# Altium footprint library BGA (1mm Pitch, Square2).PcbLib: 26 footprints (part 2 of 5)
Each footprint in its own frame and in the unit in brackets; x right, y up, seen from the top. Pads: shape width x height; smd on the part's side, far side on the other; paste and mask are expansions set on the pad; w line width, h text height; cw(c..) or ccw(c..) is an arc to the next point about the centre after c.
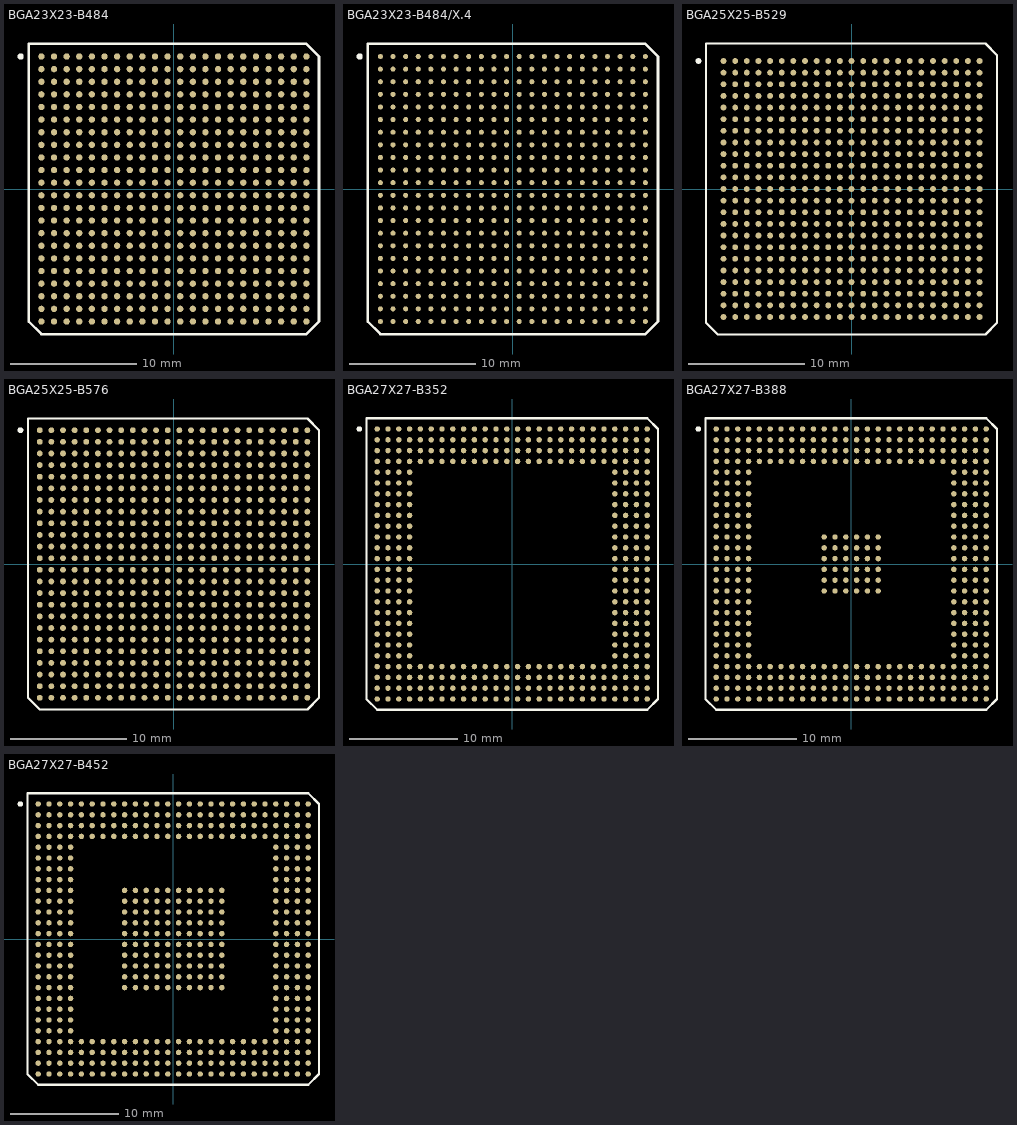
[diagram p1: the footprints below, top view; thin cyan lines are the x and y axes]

## BGA23X23-B484 [mm]
pads (484):
  round 0.5 smd: A1(-10.5,10.5) A2(-9.5,10.5) A3(-8.5,10.5) A4(-7.5,10.5) A5(-6.5,10.5) A6(-5.5,10.5) A7(-4.5,10.5) A8(-3.5,10.5) A9(-2.5,10.5) A10(-1.5,10.5) A11(-0.5,10.5) A12(0.5,10.5) A13(1.5,10.5) A14(2.5,10.5) A15(3.5,10.5) A16(4.5,10.5) A17(5.5,10.5) A18(6.5,10.5) A19(7.5,10.5) A20(8.5,10.5) A21(9.5,10.5) A22(10.5,10.5) AA1(-10.5,-9.5) AA2(-9.5,-9.5) AA3(-8.5,-9.5) AA4(-7.5,-9.5) AA5(-6.5,-9.5) AA6(-5.5,-9.5) AA7(-4.5,-9.5) AA8(-3.5,-9.5) AA9(-2.5,-9.5) AA10(-1.5,-9.5) AA11(-0.5,-9.5) AA12(0.5,-9.5) AA13(1.5,-9.5) AA14(2.5,-9.5) AA15(3.5,-9.5) AA16(4.5,-9.5) AA17(5.5,-9.5) AA18(6.5,-9.5) AA19(7.5,-9.5) AA20(8.5,-9.5) AA21(9.5,-9.5) AA22(10.5,-9.5) AB1(-10.5,-10.5) AB2(-9.5,-10.5) AB3(-8.5,-10.5) AB4(-7.5,-10.5) AB5(-6.5,-10.5) AB6(-5.5,-10.5) AB7(-4.5,-10.5) AB8(-3.5,-10.5) AB9(-2.5,-10.5) AB10(-1.5,-10.5) AB11(-0.5,-10.5) AB12(0.5,-10.5) AB13(1.5,-10.5) AB14(2.5,-10.5) AB15(3.5,-10.5) AB16(4.5,-10.5) AB17(5.5,-10.5) AB18(6.5,-10.5) AB19(7.5,-10.5) AB20(8.5,-10.5) AB21(9.5,-10.5) AB22(10.5,-10.5) B1(-10.5,9.5) B2(-9.5,9.5) B3(-8.5,9.5) B4(-7.5,9.5) B5(-6.5,9.5) B6(-5.5,9.5) B7(-4.5,9.5) B8(-3.5,9.5) B9(-2.5,9.5) B10(-1.5,9.5) B11(-0.5,9.5) B12(0.5,9.5) B13(1.5,9.5) B14(2.5,9.5) B15(3.5,9.5) B16(4.5,9.5) B17(5.5,9.5) B18(6.5,9.5) B19(7.5,9.5) B20(8.5,9.5) B21(9.5,9.5) B22(10.5,9.5) C1(-10.5,8.5) C2(-9.5,8.5) C3(-8.5,8.5) C4(-7.5,8.5) C5(-6.5,8.5) C6(-5.5,8.5) C7(-4.5,8.5) C8(-3.5,8.5) C9(-2.5,8.5) C10(-1.5,8.5) C11(-0.5,8.5) C12(0.5,8.5) C13(1.5,8.5) C14(2.5,8.5) C15(3.5,8.5) C16(4.5,8.5) C17(5.5,8.5) C18(6.5,8.5) C19(7.5,8.5) C20(8.5,8.5) C21(9.5,8.5) C22(10.5,8.5) D1(-10.5,7.5) D2(-9.5,7.5) D3(-8.5,7.5) D4(-7.5,7.5) D5(-6.5,7.5) D6(-5.5,7.5) D7(-4.5,7.5) D8(-3.5,7.5) D9(-2.5,7.5) D10(-1.5,7.5) D11(-0.5,7.5) D12(0.5,7.5) D13(1.5,7.5) D14(2.5,7.5) D15(3.5,7.5) D16(4.5,7.5) D17(5.5,7.5) D18(6.5,7.5) D19(7.5,7.5) D20(8.5,7.5) D21(9.5,7.5) D22(10.5,7.5) E1(-10.5,6.5) E2(-9.5,6.5) E3(-8.5,6.5) E4(-7.5,6.5) E5(-6.5,6.5) E6(-5.5,6.5) E7(-4.5,6.5) E8(-3.5,6.5) E9(-2.5,6.5) E10(-1.5,6.5) E11(-0.5,6.5) E12(0.5,6.5) E13(1.5,6.5) E14(2.5,6.5) E15(3.5,6.5) E16(4.5,6.5) E17(5.5,6.5) E18(6.5,6.5) E19(7.5,6.5) E20(8.5,6.5) E21(9.5,6.5) E22(10.5,6.5) F1(-10.5,5.5) F2(-9.5,5.5) F3(-8.5,5.5) F4(-7.5,5.5) F5(-6.5,5.5) F6(-5.5,5.5) F7(-4.5,5.5) F8(-3.5,5.5) F9(-2.5,5.5) F10(-1.5,5.5) F11(-0.5,5.5) F12(0.5,5.5) F13(1.5,5.5) F14(2.5,5.5) F15(3.5,5.5) F16(4.5,5.5) F17(5.5,5.5) F18(6.5,5.5) F19(7.5,5.5) F20(8.5,5.5) F21(9.5,5.5) F22(10.5,5.5) G1(-10.5,4.5) G2(-9.5,4.5) G3(-8.5,4.5) G4(-7.5,4.5) G5(-6.5,4.5) G6(-5.5,4.5) G7(-4.5,4.5) G8(-3.5,4.5) G9(-2.5,4.5) G10(-1.5,4.5) G11(-0.5,4.5) G12(0.5,4.5) G13(1.5,4.5) G14(2.5,4.5) G15(3.5,4.5) G16(4.5,4.5) G17(5.5,4.5) G18(6.5,4.5) G19(7.5,4.5) G20(8.5,4.5) G21(9.5,4.5) G22(10.5,4.5) H1(-10.5,3.5) H2(-9.5,3.5) H3(-8.5,3.5) H4(-7.5,3.5) H5(-6.5,3.5) H6(-5.5,3.5) H7(-4.5,3.5) H8(-3.5,3.5) H9(-2.5,3.5) H10(-1.5,3.5) H11(-0.5,3.5) H12(0.5,3.5) H13(1.5,3.5) H14(2.5,3.5) H15(3.5,3.5) H16(4.5,3.5) H17(5.5,3.5) H18(6.5,3.5) H19(7.5,3.5) H20(8.5,3.5) H21(9.5,3.5) H22(10.5,3.5) J1(-10.5,2.5) J2(-9.5,2.5) J3(-8.5,2.5) J4(-7.5,2.5) J5(-6.5,2.5) J6(-5.5,2.5) J7(-4.5,2.5) J8(-3.5,2.5) J9(-2.5,2.5) J10(-1.5,2.5) J11(-0.5,2.5) J12(0.5,2.5) J13(1.5,2.5) J14(2.5,2.5) J15(3.5,2.5) J16(4.5,2.5) J17(5.5,2.5) J18(6.5,2.5) J19(7.5,2.5) J20(8.5,2.5) J21(9.5,2.5) J22(10.5,2.5) K1(-10.5,1.5) K2(-9.5,1.5) K3(-8.5,1.5) K4(-7.5,1.5) K5(-6.5,1.5) K6(-5.5,1.5) K7(-4.5,1.5) K8(-3.5,1.5) K9(-2.5,1.5) K10(-1.5,1.5) K11(-0.5,1.5) K12(0.5,1.5) K13(1.5,1.5) K14(2.5,1.5) K15(3.5,1.5) K16(4.5,1.5) K17(5.5,1.5) K18(6.5,1.5) K19(7.5,1.5) K20(8.5,1.5) K21(9.5,1.5) K22(10.5,1.5) L1(-10.5,0.5) L2(-9.5,0.5) L3(-8.5,0.5) L4(-7.5,0.5) L5(-6.5,0.5) L6(-5.5,0.5) L7(-4.5,0.5) L8(-3.5,0.5) L9(-2.5,0.5) L10(-1.5,0.5) L11(-0.5,0.5) L12(0.5,0.5) L13(1.5,0.5) L14(2.5,0.5) L15(3.5,0.5) L16(4.5,0.5) L17(5.5,0.5) L18(6.5,0.5) L19(7.5,0.5) L20(8.5,0.5) L21(9.5,0.5) L22(10.5,0.5) M1(-10.5,-0.5) M2(-9.5,-0.5) M3(-8.5,-0.5) M4(-7.5,-0.5) M5(-6.5,-0.5) M6(-5.5,-0.5) M7(-4.5,-0.5) M8(-3.5,-0.5) M9(-2.5,-0.5) M10(-1.5,-0.5) M11(-0.5,-0.5) M12(0.5,-0.5) M13(1.5,-0.5) M14(2.5,-0.5) M15(3.5,-0.5) M16(4.5,-0.5) M17(5.5,-0.5) M18(6.5,-0.5) M19(7.5,-0.5) M20(8.5,-0.5) M21(9.5,-0.5) M22(10.5,-0.5) N1(-10.5,-1.5) N2(-9.5,-1.5) N3(-8.5,-1.5) N4(-7.5,-1.5) N5(-6.5,-1.5) N6(-5.5,-1.5) N7(-4.5,-1.5) N8(-3.5,-1.5) N9(-2.5,-1.5) N10(-1.5,-1.5) N11(-0.5,-1.5) N12(0.5,-1.5) N13(1.5,-1.5) N14(2.5,-1.5) N15(3.5,-1.5) N16(4.5,-1.5) N17(5.5,-1.5) N18(6.5,-1.5) N19(7.5,-1.5) N20(8.5,-1.5) N21(9.5,-1.5) N22(10.5,-1.5) P1(-10.5,-2.5) P2(-9.5,-2.5) P3(-8.5,-2.5) P4(-7.5,-2.5) P5(-6.5,-2.5) P6(-5.5,-2.5) P7(-4.5,-2.5) P8(-3.5,-2.5) P9(-2.5,-2.5) P10(-1.5,-2.5) P11(-0.5,-2.5) P12(0.5,-2.5) P13(1.5,-2.5) P14(2.5,-2.5) P15(3.5,-2.5) P16(4.5,-2.5) P17(5.5,-2.5) P18(6.5,-2.5) P19(7.5,-2.5) P20(8.5,-2.5) P21(9.5,-2.5) P22(10.5,-2.5) R1(-10.5,-3.5) R2(-9.5,-3.5) R3(-8.5,-3.5) R4(-7.5,-3.5) R5(-6.5,-3.5) R6(-5.5,-3.5) R7(-4.5,-3.5) R8(-3.5,-3.5) R9(-2.5,-3.5) R10(-1.5,-3.5) R11(-0.5,-3.5) R12(0.5,-3.5) R13(1.5,-3.5) R14(2.5,-3.5) R15(3.5,-3.5) R16(4.5,-3.5) R17(5.5,-3.5) R18(6.5,-3.5) R19(7.5,-3.5) R20(8.5,-3.5) R21(9.5,-3.5) R22(10.5,-3.5) T1(-10.5,-4.5) T2(-9.5,-4.5) T3(-8.5,-4.5) T4(-7.5,-4.5) T5(-6.5,-4.5) T6(-5.5,-4.5) T7(-4.5,-4.5) T8(-3.5,-4.5) T9(-2.5,-4.5) T10(-1.5,-4.5) T11(-0.5,-4.5) T12(0.5,-4.5) T13(1.5,-4.5) T14(2.5,-4.5) T15(3.5,-4.5) T16(4.5,-4.5) T17(5.5,-4.5) T18(6.5,-4.5) T19(7.5,-4.5) T20(8.5,-4.5) T21(9.5,-4.5) T22(10.5,-4.5) U1(-10.5,-5.5) U2(-9.5,-5.5) U3(-8.5,-5.5) U4(-7.5,-5.5) U5(-6.5,-5.5) U6(-5.5,-5.5) U7(-4.5,-5.5) U8(-3.5,-5.5) U9(-2.5,-5.5) U10(-1.5,-5.5) U11(-0.5,-5.5) U12(0.5,-5.5) U13(1.5,-5.5) U14(2.5,-5.5) U15(3.5,-5.5) U16(4.5,-5.5) U17(5.5,-5.5) U18(6.5,-5.5) U19(7.5,-5.5) U20(8.5,-5.5) U21(9.5,-5.5) U22(10.5,-5.5) V1(-10.5,-6.5) V2(-9.5,-6.5) V3(-8.5,-6.5) V4(-7.5,-6.5) V5(-6.5,-6.5) V6(-5.5,-6.5) V7(-4.5,-6.5) V8(-3.5,-6.5) V9(-2.5,-6.5) V10(-1.5,-6.5) V11(-0.5,-6.5) V12(0.5,-6.5) V13(1.5,-6.5) V14(2.5,-6.5) V15(3.5,-6.5) V16(4.5,-6.5) V17(5.5,-6.5) V18(6.5,-6.5) V19(7.5,-6.5) V20(8.5,-6.5) V21(9.5,-6.5) V22(10.5,-6.5) W1(-10.5,-7.5) W2(-9.5,-7.5) W3(-8.5,-7.5) W4(-7.5,-7.5) W5(-6.5,-7.5) W6(-5.5,-7.5) W7(-4.5,-7.5) W8(-3.5,-7.5) W9(-2.5,-7.5) W10(-1.5,-7.5) W11(-0.5,-7.5) W12(0.5,-7.5) W13(1.5,-7.5) W14(2.5,-7.5) W15(3.5,-7.5) W16(4.5,-7.5) W17(5.5,-7.5) W18(6.5,-7.5) W19(7.5,-7.5) W20(8.5,-7.5) W21(9.5,-7.5) W22(10.5,-7.5) Y1(-10.5,-8.5) Y2(-9.5,-8.5) Y3(-8.5,-8.5) Y4(-7.5,-8.5) Y5(-6.5,-8.5) Y6(-5.5,-8.5) Y7(-4.5,-8.5) Y8(-3.5,-8.5) Y9(-2.5,-8.5) Y10(-1.5,-8.5) Y11(-0.5,-8.5) Y12(0.5,-8.5) Y13(1.5,-8.5) Y14(2.5,-8.5) Y15(3.5,-8.5) Y16(4.5,-8.5) Y17(5.5,-8.5) Y18(6.5,-8.5) Y19(7.5,-8.5) Y20(8.5,-8.5) Y21(9.5,-8.5) Y22(10.5,-8.5)
Top Overlay:
  circle w0.25: c-12.15,10.5 r0.125
  lines w0.2: 10.5,-11.5 11.5,-10.5 11.5,10.5 ; 10.5,-11.5 10.5,-11.5 ; 10.5,-11.5 -10.5,-11.5 -11.5,-10.5 -11.5,11.5 10.5,11.5 11.5,10.5 ; 11.5,10.5 11.5,10.5

## BGA23X23-B484/X.4 [mm]
pads (484):
  round 0.4 smd: A1(-10.5,10.5) A2(-9.5,10.5) A3(-8.5,10.5) A4(-7.5,10.5) A5(-6.5,10.5) A6(-5.5,10.5) A7(-4.5,10.5) A8(-3.5,10.5) A9(-2.5,10.5) A10(-1.5,10.5) A11(-0.5,10.5) A12(0.5,10.5) A13(1.5,10.5) A14(2.5,10.5) A15(3.5,10.5) A16(4.5,10.5) A17(5.5,10.5) A18(6.5,10.5) A19(7.5,10.5) A20(8.5,10.5) A21(9.5,10.5) A22(10.5,10.5) AA1(-10.5,-9.5) AA2(-9.5,-9.5) AA3(-8.5,-9.5) AA4(-7.5,-9.5) AA5(-6.5,-9.5) AA6(-5.5,-9.5) AA7(-4.5,-9.5) AA8(-3.5,-9.5) AA9(-2.5,-9.5) AA10(-1.5,-9.5) AA11(-0.5,-9.5) AA12(0.5,-9.5) AA13(1.5,-9.5) AA14(2.5,-9.5) AA15(3.5,-9.5) AA16(4.5,-9.5) AA17(5.5,-9.5) AA18(6.5,-9.5) AA19(7.5,-9.5) AA20(8.5,-9.5) AA21(9.5,-9.5) AA22(10.5,-9.5) AB1(-10.5,-10.5) AB2(-9.5,-10.5) AB3(-8.5,-10.5) AB4(-7.5,-10.5) AB5(-6.5,-10.5) AB6(-5.5,-10.5) AB7(-4.5,-10.5) AB8(-3.5,-10.5) AB9(-2.5,-10.5) AB10(-1.5,-10.5) AB11(-0.5,-10.5) AB12(0.5,-10.5) AB13(1.5,-10.5) AB14(2.5,-10.5) AB15(3.5,-10.5) AB16(4.5,-10.5) AB17(5.5,-10.5) AB18(6.5,-10.5) AB19(7.5,-10.5) AB20(8.5,-10.5) AB21(9.5,-10.5) AB22(10.5,-10.5) B1(-10.5,9.5) B2(-9.5,9.5) B3(-8.5,9.5) B4(-7.5,9.5) B5(-6.5,9.5) B6(-5.5,9.5) B7(-4.5,9.5) B8(-3.5,9.5) B9(-2.5,9.5) B10(-1.5,9.5) B11(-0.5,9.5) B12(0.5,9.5) B13(1.5,9.5) B14(2.5,9.5) B15(3.5,9.5) B16(4.5,9.5) B17(5.5,9.5) B18(6.5,9.5) B19(7.5,9.5) B20(8.5,9.5) B21(9.5,9.5) B22(10.5,9.5) C1(-10.5,8.5) C2(-9.5,8.5) C3(-8.5,8.5) C4(-7.5,8.5) C5(-6.5,8.5) C6(-5.5,8.5) C7(-4.5,8.5) C8(-3.5,8.5) C9(-2.5,8.5) C10(-1.5,8.5) C11(-0.5,8.5) C12(0.5,8.5) C13(1.5,8.5) C14(2.5,8.5) C15(3.5,8.5) C16(4.5,8.5) C17(5.5,8.5) C18(6.5,8.5) C19(7.5,8.5) C20(8.5,8.5) C21(9.5,8.5) C22(10.5,8.5) D1(-10.5,7.5) D2(-9.5,7.5) D3(-8.5,7.5) D4(-7.5,7.5) D5(-6.5,7.5) D6(-5.5,7.5) D7(-4.5,7.5) D8(-3.5,7.5) D9(-2.5,7.5) D10(-1.5,7.5) D11(-0.5,7.5) D12(0.5,7.5) D13(1.5,7.5) D14(2.5,7.5) D15(3.5,7.5) D16(4.5,7.5) D17(5.5,7.5) D18(6.5,7.5) D19(7.5,7.5) D20(8.5,7.5) D21(9.5,7.5) D22(10.5,7.5) E1(-10.5,6.5) E2(-9.5,6.5) E3(-8.5,6.5) E4(-7.5,6.5) E5(-6.5,6.5) E6(-5.5,6.5) E7(-4.5,6.5) E8(-3.5,6.5) E9(-2.5,6.5) E10(-1.5,6.5) E11(-0.5,6.5) E12(0.5,6.5) E13(1.5,6.5) E14(2.5,6.5) E15(3.5,6.5) E16(4.5,6.5) E17(5.5,6.5) E18(6.5,6.5) E19(7.5,6.5) E20(8.5,6.5) E21(9.5,6.5) E22(10.5,6.5) F1(-10.5,5.5) F2(-9.5,5.5) F3(-8.5,5.5) F4(-7.5,5.5) F5(-6.5,5.5) F6(-5.5,5.5) F7(-4.5,5.5) F8(-3.5,5.5) F9(-2.5,5.5) F10(-1.5,5.5) F11(-0.5,5.5) F12(0.5,5.5) F13(1.5,5.5) F14(2.5,5.5) F15(3.5,5.5) F16(4.5,5.5) F17(5.5,5.5) F18(6.5,5.5) F19(7.5,5.5) F20(8.5,5.5) F21(9.5,5.5) F22(10.5,5.5) G1(-10.5,4.5) G2(-9.5,4.5) G3(-8.5,4.5) G4(-7.5,4.5) G5(-6.5,4.5) G6(-5.5,4.5) G7(-4.5,4.5) G8(-3.5,4.5) G9(-2.5,4.5) G10(-1.5,4.5) G11(-0.5,4.5) G12(0.5,4.5) G13(1.5,4.5) G14(2.5,4.5) G15(3.5,4.5) G16(4.5,4.5) G17(5.5,4.5) G18(6.5,4.5) G19(7.5,4.5) G20(8.5,4.5) G21(9.5,4.5) G22(10.5,4.5) H1(-10.5,3.5) H2(-9.5,3.5) H3(-8.5,3.5) H4(-7.5,3.5) H5(-6.5,3.5) H6(-5.5,3.5) H7(-4.5,3.5) H8(-3.5,3.5) H9(-2.5,3.5) H10(-1.5,3.5) H11(-0.5,3.5) H12(0.5,3.5) H13(1.5,3.5) H14(2.5,3.5) H15(3.5,3.5) H16(4.5,3.5) H17(5.5,3.5) H18(6.5,3.5) H19(7.5,3.5) H20(8.5,3.5) H21(9.5,3.5) H22(10.5,3.5) J1(-10.5,2.5) J2(-9.5,2.5) J3(-8.5,2.5) J4(-7.5,2.5) J5(-6.5,2.5) J6(-5.5,2.5) J7(-4.5,2.5) J8(-3.5,2.5) J9(-2.5,2.5) J10(-1.5,2.5) J11(-0.5,2.5) J12(0.5,2.5) J13(1.5,2.5) J14(2.5,2.5) J15(3.5,2.5) J16(4.5,2.5) J17(5.5,2.5) J18(6.5,2.5) J19(7.5,2.5) J20(8.5,2.5) J21(9.5,2.5) J22(10.5,2.5) K1(-10.5,1.5) K2(-9.5,1.5) K3(-8.5,1.5) K4(-7.5,1.5) K5(-6.5,1.5) K6(-5.5,1.5) K7(-4.5,1.5) K8(-3.5,1.5) K9(-2.5,1.5) K10(-1.5,1.5) K11(-0.5,1.5) K12(0.5,1.5) K13(1.5,1.5) K14(2.5,1.5) K15(3.5,1.5) K16(4.5,1.5) K17(5.5,1.5) K18(6.5,1.5) K19(7.5,1.5) K20(8.5,1.5) K21(9.5,1.5) K22(10.5,1.5) L1(-10.5,0.5) L2(-9.5,0.5) L3(-8.5,0.5) L4(-7.5,0.5) L5(-6.5,0.5) L6(-5.5,0.5) L7(-4.5,0.5) L8(-3.5,0.5) L9(-2.5,0.5) L10(-1.5,0.5) L11(-0.5,0.5) L12(0.5,0.5) L13(1.5,0.5) L14(2.5,0.5) L15(3.5,0.5) L16(4.5,0.5) L17(5.5,0.5) L18(6.5,0.5) L19(7.5,0.5) L20(8.5,0.5) L21(9.5,0.5) L22(10.5,0.5) M1(-10.5,-0.5) M2(-9.5,-0.5) M3(-8.5,-0.5) M4(-7.5,-0.5) M5(-6.5,-0.5) M6(-5.5,-0.5) M7(-4.5,-0.5) M8(-3.5,-0.5) M9(-2.5,-0.5) M10(-1.5,-0.5) M11(-0.5,-0.5) M12(0.5,-0.5) M13(1.5,-0.5) M14(2.5,-0.5) M15(3.5,-0.5) M16(4.5,-0.5) M17(5.5,-0.5) M18(6.5,-0.5) M19(7.5,-0.5) M20(8.5,-0.5) M21(9.5,-0.5) M22(10.5,-0.5) N1(-10.5,-1.5) N2(-9.5,-1.5) N3(-8.5,-1.5) N4(-7.5,-1.5) N5(-6.5,-1.5) N6(-5.5,-1.5) N7(-4.5,-1.5) N8(-3.5,-1.5) N9(-2.5,-1.5) N10(-1.5,-1.5) N11(-0.5,-1.5) N12(0.5,-1.5) N13(1.5,-1.5) N14(2.5,-1.5) N15(3.5,-1.5) N16(4.5,-1.5) N17(5.5,-1.5) N18(6.5,-1.5) N19(7.5,-1.5) N20(8.5,-1.5) N21(9.5,-1.5) N22(10.5,-1.5) P1(-10.5,-2.5) P2(-9.5,-2.5) P3(-8.5,-2.5) P4(-7.5,-2.5) P5(-6.5,-2.5) P6(-5.5,-2.5) P7(-4.5,-2.5) P8(-3.5,-2.5) P9(-2.5,-2.5) P10(-1.5,-2.5) P11(-0.5,-2.5) P12(0.5,-2.5) P13(1.5,-2.5) P14(2.5,-2.5) P15(3.5,-2.5) P16(4.5,-2.5) P17(5.5,-2.5) P18(6.5,-2.5) P19(7.5,-2.5) P20(8.5,-2.5) P21(9.5,-2.5) P22(10.5,-2.5) R1(-10.5,-3.5) R2(-9.5,-3.5) R3(-8.5,-3.5) R4(-7.5,-3.5) R5(-6.5,-3.5) R6(-5.5,-3.5) R7(-4.5,-3.5) R8(-3.5,-3.5) R9(-2.5,-3.5) R10(-1.5,-3.5) R11(-0.5,-3.5) R12(0.5,-3.5) R13(1.5,-3.5) R14(2.5,-3.5) R15(3.5,-3.5) R16(4.5,-3.5) R17(5.5,-3.5) R18(6.5,-3.5) R19(7.5,-3.5) R20(8.5,-3.5) R21(9.5,-3.5) R22(10.5,-3.5) T1(-10.5,-4.5) T2(-9.5,-4.5) T3(-8.5,-4.5) T4(-7.5,-4.5) T5(-6.5,-4.5) T6(-5.5,-4.5) T7(-4.5,-4.5) T8(-3.5,-4.5) T9(-2.5,-4.5) T10(-1.5,-4.5) T11(-0.5,-4.5) T12(0.5,-4.5) T13(1.5,-4.5) T14(2.5,-4.5) T15(3.5,-4.5) T16(4.5,-4.5) T17(5.5,-4.5) T18(6.5,-4.5) T19(7.5,-4.5) T20(8.5,-4.5) T21(9.5,-4.5) T22(10.5,-4.5) U1(-10.5,-5.5) U2(-9.5,-5.5) U3(-8.5,-5.5) U4(-7.5,-5.5) U5(-6.5,-5.5) U6(-5.5,-5.5) U7(-4.5,-5.5) U8(-3.5,-5.5) U9(-2.5,-5.5) U10(-1.5,-5.5) U11(-0.5,-5.5) U12(0.5,-5.5) U13(1.5,-5.5) U14(2.5,-5.5) U15(3.5,-5.5) U16(4.5,-5.5) U17(5.5,-5.5) U18(6.5,-5.5) U19(7.5,-5.5) U20(8.5,-5.5) U21(9.5,-5.5) U22(10.5,-5.5) V1(-10.5,-6.5) V2(-9.5,-6.5) V3(-8.5,-6.5) V4(-7.5,-6.5) V5(-6.5,-6.5) V6(-5.5,-6.5) V7(-4.5,-6.5) V8(-3.5,-6.5) V9(-2.5,-6.5) V10(-1.5,-6.5) V11(-0.5,-6.5) V12(0.5,-6.5) V13(1.5,-6.5) V14(2.5,-6.5) V15(3.5,-6.5) V16(4.5,-6.5) V17(5.5,-6.5) V18(6.5,-6.5) V19(7.5,-6.5) V20(8.5,-6.5) V21(9.5,-6.5) V22(10.5,-6.5) W1(-10.5,-7.5) W2(-9.5,-7.5) W3(-8.5,-7.5) W4(-7.5,-7.5) W5(-6.5,-7.5) W6(-5.5,-7.5) W7(-4.5,-7.5) W8(-3.5,-7.5) W9(-2.5,-7.5) W10(-1.5,-7.5) W11(-0.5,-7.5) W12(0.5,-7.5) W13(1.5,-7.5) W14(2.5,-7.5) W15(3.5,-7.5) W16(4.5,-7.5) W17(5.5,-7.5) W18(6.5,-7.5) W19(7.5,-7.5) W20(8.5,-7.5) W21(9.5,-7.5) W22(10.5,-7.5) Y1(-10.5,-8.5) Y2(-9.5,-8.5) Y3(-8.5,-8.5) Y4(-7.5,-8.5) Y5(-6.5,-8.5) Y6(-5.5,-8.5) Y7(-4.5,-8.5) Y8(-3.5,-8.5) Y9(-2.5,-8.5) Y10(-1.5,-8.5) Y11(-0.5,-8.5) Y12(0.5,-8.5) Y13(1.5,-8.5) Y14(2.5,-8.5) Y15(3.5,-8.5) Y16(4.5,-8.5) Y17(5.5,-8.5) Y18(6.5,-8.5) Y19(7.5,-8.5) Y20(8.5,-8.5) Y21(9.5,-8.5) Y22(10.5,-8.5)
Top Overlay:
  circle w0.25: c-12.15,10.5 r0.125
  lines w0.2: -11.5,-10.5 -10.5,-11.5 10.5,-11.5 11.5,-10.5 11.5,10.5 10.5,11.5 -11.5,11.5 -11.5,-10.5

## BGA25X25-B529 [mm]
pads (529):
  round 0.5 smd: A1(-11,11) A2(-10,11) A3(-9,11) A4(-8,11) A5(-7,11) A6(-6,11) A7(-5,11) A8(-4,11) A9(-3,11) A10(-2,11) A11(-1,11) A12(0,11) A13(1,11) A14(2,11) A15(3,11) A16(4,11) A17(5,11) A18(6,11) A19(7,11) A20(8,11) A21(9,11) A22(10,11) A23(11,11) AA1(-11,-9) AA2(-10,-9) AA3(-9,-9) AA4(-8,-9) AA5(-7,-9) AA6(-6,-9) AA7(-5,-9) AA8(-4,-9) AA9(-3,-9) AA10(-2,-9) AA11(-1,-9) AA12(0,-9) AA13(1,-9) AA14(2,-9) AA15(3,-9) AA16(4,-9) AA17(5,-9) AA18(6,-9) AA19(7,-9) AA20(8,-9) AA21(9,-9) AA22(10,-9) AA23(11,-9) AB1(-11,-10) AB2(-10,-10) AB3(-9,-10) AB4(-8,-10) AB5(-7,-10) AB6(-6,-10) AB7(-5,-10) AB8(-4,-10) AB9(-3,-10) AB10(-2,-10) AB11(-1,-10) AB12(0,-10) AB13(1,-10) AB14(2,-10) AB15(3,-10) AB16(4,-10) AB17(5,-10) AB18(6,-10) AB19(7,-10) AB20(8,-10) AB21(9,-10) AB22(10,-10) AB23(11,-10) AC1(-11,-11) AC2(-10,-11) AC3(-9,-11) AC4(-8,-11) AC5(-7,-11) AC6(-6,-11) AC7(-5,-11) AC8(-4,-11) AC9(-3,-11) AC10(-2,-11) AC11(-1,-11) AC12(0,-11) AC13(1,-11) AC14(2,-11) AC15(3,-11) AC16(4,-11) AC17(5,-11) AC18(6,-11) AC19(7,-11) AC20(8,-11) AC21(9,-11) AC22(10,-11) AC23(11,-11) B1(-11,10) B2(-10,10) B3(-9,10) B4(-8,10) B5(-7,10) B6(-6,10) B7(-5,10) B8(-4,10) B9(-3,10) B10(-2,10) B11(-1,10) B12(0,10) B13(1,10) B14(2,10) B15(3,10) B16(4,10) B17(5,10) B18(6,10) B19(7,10) B20(8,10) B21(9,10) B22(10,10) B23(11,10) C1(-11,9) C2(-10,9) C3(-9,9) C4(-8,9) C5(-7,9) C6(-6,9) C7(-5,9) C8(-4,9) C9(-3,9) C10(-2,9) C11(-1,9) C12(0,9) C13(1,9) C14(2,9) C15(3,9) C16(4,9) C17(5,9) C18(6,9) C19(7,9) C20(8,9) C21(9,9) C22(10,9) C23(11,9) D1(-11,8) D2(-10,8) D3(-9,8) D4(-8,8) D5(-7,8) D6(-6,8) D7(-5,8) D8(-4,8) D9(-3,8) D10(-2,8) D11(-1,8) D12(0,8) D13(1,8) D14(2,8) D15(3,8) D16(4,8) D17(5,8) D18(6,8) D19(7,8) D20(8,8) D21(9,8) D22(10,8) D23(11,8) E1(-11,7) E2(-10,7) E3(-9,7) E4(-8,7) E5(-7,7) E6(-6,7) E7(-5,7) E8(-4,7) E9(-3,7) E10(-2,7) E11(-1,7) E12(0,7) E13(1,7) E14(2,7) E15(3,7) E16(4,7) E17(5,7) E18(6,7) E19(7,7) E20(8,7) E21(9,7) E22(10,7) E23(11,7) F1(-11,6) F2(-10,6) F3(-9,6) F4(-8,6) F5(-7,6) F6(-6,6) F7(-5,6) F8(-4,6) F9(-3,6) F10(-2,6) F11(-1,6) F12(0,6) F13(1,6) F14(2,6) F15(3,6) F16(4,6) F17(5,6) F18(6,6) F19(7,6) F20(8,6) F21(9,6) F22(10,6) F23(11,6) G1(-11,5) G2(-10,5) G3(-9,5) G4(-8,5) G5(-7,5) G6(-6,5) G7(-5,5) G8(-4,5) G9(-3,5) G10(-2,5) G11(-1,5) G12(0,5) G13(1,5) G14(2,5) G15(3,5) G16(4,5) G17(5,5) G18(6,5) G19(7,5) G20(8,5) G21(9,5) G22(10,5) G23(11,5) H1(-11,4) H2(-10,4) H3(-9,4) H4(-8,4) H5(-7,4) H6(-6,4) H7(-5,4) H8(-4,4) H9(-3,4) H10(-2,4) H11(-1,4) H12(0,4) H13(1,4) H14(2,4) H15(3,4) H16(4,4) H17(5,4) H18(6,4) H19(7,4) H20(8,4) H21(9,4) H22(10,4) H23(11,4) J1(-11,3) J2(-10,3) J3(-9,3) J4(-8,3) J5(-7,3) J6(-6,3) J7(-5,3) J8(-4,3) J9(-3,3) J10(-2,3) J11(-1,3) J12(0,3) J13(1,3) J14(2,3) J15(3,3) J16(4,3) J17(5,3) J18(6,3) J19(7,3) J20(8,3) J21(9,3) J22(10,3) J23(11,3) K1(-11,2) K2(-10,2) K3(-9,2) K4(-8,2) K5(-7,2) K6(-6,2) K7(-5,2) K8(-4,2) K9(-3,2) K10(-2,2) K11(-1,2) K12(0,2) K13(1,2) K14(2,2) K15(3,2) K16(4,2) K17(5,2) K18(6,2) K19(7,2) K20(8,2) K21(9,2) K22(10,2) K23(11,2) L1(-11,1) L2(-10,1) L3(-9,1) L4(-8,1) L5(-7,1) L6(-6,1) L7(-5,1) L8(-4,1) L9(-3,1) L10(-2,1) L11(-1,1) L12(0,1) L13(1,1) L14(2,1) L15(3,1) L16(4,1) L17(5,1) L18(6,1) L19(7,1) L20(8,1) L21(9,1) L22(10,1) L23(11,1) M1(-11,0) M2(-10,0) M3(-9,0) M4(-8,0) M5(-7,0) M6(-6,0) M7(-5,0) M8(-4,0) M9(-3,0) M10(-2,0) M11(-1,0) M12(0,0) M13(1,0) M14(2,0) M15(3,0) M16(4,0) M17(5,0) M18(6,0) M19(7,0) M20(8,0) M21(9,0) M22(10,0) M23(11,0) N1(-11,-1) N2(-10,-1) N3(-9,-1) N4(-8,-1) N5(-7,-1) N6(-6,-1) N7(-5,-1) N8(-4,-1) N9(-3,-1) N10(-2,-1) N11(-1,-1) N12(0,-1) N13(1,-1) N14(2,-1) N15(3,-1) N16(4,-1) N17(5,-1) N18(6,-1) N19(7,-1) N20(8,-1) N21(9,-1) N22(10,-1) N23(11,-1) P1(-11,-2) P2(-10,-2) P3(-9,-2) P4(-8,-2) P5(-7,-2) P6(-6,-2) P7(-5,-2) P8(-4,-2) P9(-3,-2) P10(-2,-2) P11(-1,-2) P12(0,-2) P13(1,-2) P14(2,-2) P15(3,-2) P16(4,-2) P17(5,-2) P18(6,-2) P19(7,-2) P20(8,-2) P21(9,-2) P22(10,-2) P23(11,-2) R1(-11,-3) R2(-10,-3) R3(-9,-3) R4(-8,-3) R5(-7,-3) R6(-6,-3) R7(-5,-3) R8(-4,-3) R9(-3,-3) R10(-2,-3) R11(-1,-3) R12(0,-3) R13(1,-3) R14(2,-3) R15(3,-3) R16(4,-3) R17(5,-3) R18(6,-3) R19(7,-3) R20(8,-3) R21(9,-3) R22(10,-3) R23(11,-3) T1(-11,-4) T2(-10,-4) T3(-9,-4) T4(-8,-4) T5(-7,-4) T6(-6,-4) T7(-5,-4) T8(-4,-4) T9(-3,-4) T10(-2,-4) T11(-1,-4) T12(0,-4) T13(1,-4) T14(2,-4) T15(3,-4) T16(4,-4) T17(5,-4) T18(6,-4) T19(7,-4) T20(8,-4) T21(9,-4) T22(10,-4) T23(11,-4) U1(-11,-5) U2(-10,-5) U3(-9,-5) U4(-8,-5) U5(-7,-5) U6(-6,-5) U7(-5,-5) U8(-4,-5) U9(-3,-5) U10(-2,-5) U11(-1,-5) U12(0,-5) U13(1,-5) U14(2,-5) U15(3,-5) U16(4,-5) U17(5,-5) U18(6,-5) U19(7,-5) U20(8,-5) U21(9,-5) U22(10,-5) U23(11,-5) V1(-11,-6) V2(-10,-6) V3(-9,-6) V4(-8,-6) V5(-7,-6) V6(-6,-6) V7(-5,-6) V8(-4,-6) V9(-3,-6) V10(-2,-6) V11(-1,-6) V12(0,-6) V13(1,-6) V14(2,-6) V15(3,-6) V16(4,-6) V17(5,-6) V18(6,-6) V19(7,-6) V20(8,-6) V21(9,-6) V22(10,-6) V23(11,-6) W1(-11,-7) W2(-10,-7) W3(-9,-7) W4(-8,-7) W5(-7,-7) W6(-6,-7) W7(-5,-7) W8(-4,-7) W9(-3,-7) W10(-2,-7) W11(-1,-7) W12(0,-7) W13(1,-7) W14(2,-7) W15(3,-7) W16(4,-7) W17(5,-7) W18(6,-7) W19(7,-7) W20(8,-7) W21(9,-7) W22(10,-7) W23(11,-7) Y1(-11,-8) Y2(-10,-8) Y3(-9,-8) Y4(-8,-8) Y5(-7,-8) Y6(-6,-8) Y7(-5,-8) Y8(-4,-8) Y9(-3,-8) Y10(-2,-8) Y11(-1,-8) Y12(0,-8) Y13(1,-8) Y14(2,-8) Y15(3,-8) Y16(4,-8) Y17(5,-8) Y18(6,-8) Y19(7,-8) Y20(8,-8) Y21(9,-8) Y22(10,-8) Y23(11,-8)
Top Overlay:
  circle w0.25: c-13.155,11 r0.125
  lines w0.2: -12.5,-11.5 -12.5,12.5 11.5,12.5 12.5,11.5 12.5,-11.5 11.5,-12.5 -11.5,-12.5 -12.5,-11.5

## BGA25X25-B576 [mm]
pads (576):
  round 0.5 smd: A1(-11.5,11.5) A2(-10.5,11.5) A3(-9.5,11.5) A4(-8.5,11.5) A5(-7.5,11.5) A6(-6.5,11.5) A7(-5.5,11.5) A8(-4.5,11.5) A9(-3.5,11.5) A10(-2.5,11.5) A11(-1.5,11.5) A12(-0.5,11.5) A13(0.5,11.5) A14(1.5,11.5) A15(2.5,11.5) A16(3.5,11.5) A17(4.5,11.5) A18(5.5,11.5) A19(6.5,11.5) A20(7.5,11.5) A21(8.5,11.5) A22(9.5,11.5) A23(10.5,11.5) A24(11.5,11.5) AA1(-11.5,-8.5) AA2(-10.5,-8.5) AA3(-9.5,-8.5) AA4(-8.5,-8.5) AA5(-7.5,-8.5) AA6(-6.5,-8.5) AA7(-5.5,-8.5) AA8(-4.5,-8.5) AA9(-3.5,-8.5) AA10(-2.5,-8.5) AA11(-1.5,-8.5) AA12(-0.5,-8.5) AA13(0.5,-8.5) AA14(1.5,-8.5) AA15(2.5,-8.5) AA16(3.5,-8.5) AA17(4.5,-8.5) AA18(5.5,-8.5) AA19(6.5,-8.5) AA20(7.5,-8.5) AA21(8.5,-8.5) AA22(9.5,-8.5) AA23(10.5,-8.5) AA24(11.5,-8.5) AB1(-11.5,-9.5) AB2(-10.5,-9.5) AB3(-9.5,-9.5) AB4(-8.5,-9.5) AB5(-7.5,-9.5) AB6(-6.5,-9.5) AB7(-5.5,-9.5) AB8(-4.5,-9.5) AB9(-3.5,-9.5) AB10(-2.5,-9.5) AB11(-1.5,-9.5) AB12(-0.5,-9.5) AB13(0.5,-9.5) AB14(1.5,-9.5) AB15(2.5,-9.5) AB16(3.5,-9.5) AB17(4.5,-9.5) AB18(5.5,-9.5) AB19(6.5,-9.5) AB20(7.5,-9.5) AB21(8.5,-9.5) AB22(9.5,-9.5) AB23(10.5,-9.5) AB24(11.5,-9.5) AC1(-11.5,-10.5) AC2(-10.5,-10.5) AC3(-9.5,-10.5) AC4(-8.5,-10.5) AC5(-7.5,-10.5) AC6(-6.5,-10.5) AC7(-5.5,-10.5) AC8(-4.5,-10.5) AC9(-3.5,-10.5) AC10(-2.5,-10.5) AC11(-1.5,-10.5) AC12(-0.5,-10.5) AC13(0.5,-10.5) AC14(1.5,-10.5) AC15(2.5,-10.5) AC16(3.5,-10.5) AC17(4.5,-10.5) AC18(5.5,-10.5) AC19(6.5,-10.5) AC20(7.5,-10.5) AC21(8.5,-10.5) AC22(9.5,-10.5) AC23(10.5,-10.5) AC24(11.5,-10.5) AD1(-11.5,-11.5) AD2(-10.5,-11.5) AD3(-9.5,-11.5) AD4(-8.5,-11.5) AD5(-7.5,-11.5) AD6(-6.5,-11.5) AD7(-5.5,-11.5) AD8(-4.5,-11.5) AD9(-3.5,-11.5) AD10(-2.5,-11.5) AD11(-1.5,-11.5) AD12(-0.5,-11.5) AD13(0.5,-11.5) AD14(1.5,-11.5) AD15(2.5,-11.5) AD16(3.5,-11.5) AD17(4.5,-11.5) AD18(5.5,-11.5) AD19(6.5,-11.5) AD20(7.5,-11.5) AD21(8.5,-11.5) AD22(9.5,-11.5) AD23(10.5,-11.5) AD24(11.5,-11.5) B1(-11.5,10.5) B2(-10.5,10.5) B3(-9.5,10.5) B4(-8.5,10.5) B5(-7.5,10.5) B6(-6.5,10.5) B7(-5.5,10.5) B8(-4.5,10.5) B9(-3.5,10.5) B10(-2.5,10.5) B11(-1.5,10.5) B12(-0.5,10.5) B13(0.5,10.5) B14(1.5,10.5) B15(2.5,10.5) B16(3.5,10.5) B17(4.5,10.5) B18(5.5,10.5) B19(6.5,10.5) B20(7.5,10.5) B21(8.5,10.5) B22(9.5,10.5) B23(10.5,10.5) B24(11.5,10.5) C1(-11.5,9.5) C2(-10.5,9.5) C3(-9.5,9.5) C4(-8.5,9.5) C5(-7.5,9.5) C6(-6.5,9.5) C7(-5.5,9.5) C8(-4.5,9.5) C9(-3.5,9.5) C10(-2.5,9.5) C11(-1.5,9.5) C12(-0.5,9.5) C13(0.5,9.5) C14(1.5,9.5) C15(2.5,9.5) C16(3.5,9.5) C17(4.5,9.5) C18(5.5,9.5) C19(6.5,9.5) C20(7.5,9.5) C21(8.5,9.5) C22(9.5,9.5) C23(10.5,9.5) C24(11.5,9.5) D1(-11.5,8.5) D2(-10.5,8.5) D3(-9.5,8.5) D4(-8.5,8.5) D5(-7.5,8.5) D6(-6.5,8.5) D7(-5.5,8.5) D8(-4.5,8.5) D9(-3.5,8.5) D10(-2.5,8.5) D11(-1.5,8.5) D12(-0.5,8.5) D13(0.5,8.5) D14(1.5,8.5) D15(2.5,8.5) D16(3.5,8.5) D17(4.5,8.5) D18(5.5,8.5) D19(6.5,8.5) D20(7.5,8.5) D21(8.5,8.5) D22(9.5,8.5) D23(10.5,8.5) D24(11.5,8.5) E1(-11.5,7.5) E2(-10.5,7.5) E3(-9.5,7.5) E4(-8.5,7.5) E5(-7.5,7.5) E6(-6.5,7.5) E7(-5.5,7.5) E8(-4.5,7.5) E9(-3.5,7.5) E10(-2.5,7.5) E11(-1.5,7.5) E12(-0.5,7.5) E13(0.5,7.5) E14(1.5,7.5) E15(2.5,7.5) E16(3.5,7.5) E17(4.5,7.5) E18(5.5,7.5) E19(6.5,7.5) E20(7.5,7.5) E21(8.5,7.5) E22(9.5,7.5) E23(10.5,7.5) E24(11.5,7.5) F1(-11.5,6.5) F2(-10.5,6.5) F3(-9.5,6.5) F4(-8.5,6.5) F5(-7.5,6.5) F6(-6.5,6.5) F7(-5.5,6.5) F8(-4.5,6.5) F9(-3.5,6.5) F10(-2.5,6.5) F11(-1.5,6.5) F12(-0.5,6.5) F13(0.5,6.5) F14(1.5,6.5) F15(2.5,6.5) F16(3.5,6.5) F17(4.5,6.5) F18(5.5,6.5) F19(6.5,6.5) F20(7.5,6.5) F21(8.5,6.5) F22(9.5,6.5) F23(10.5,6.5) F24(11.5,6.5) G1(-11.5,5.5) G2(-10.5,5.5) G3(-9.5,5.5) G4(-8.5,5.5) G5(-7.5,5.5) G6(-6.5,5.5) G7(-5.5,5.5) G8(-4.5,5.5) G9(-3.5,5.5) G10(-2.5,5.5) G11(-1.5,5.5) G12(-0.5,5.5) G13(0.5,5.5) G14(1.5,5.5) G15(2.5,5.5) G16(3.5,5.5) G17(4.5,5.5) G18(5.5,5.5) G19(6.5,5.5) G20(7.5,5.5) G21(8.5,5.5) G22(9.5,5.5) G23(10.5,5.5) G24(11.5,5.5) H1(-11.5,4.5) H2(-10.5,4.5) H3(-9.5,4.5) H4(-8.5,4.5) H5(-7.5,4.5) H6(-6.5,4.5) H7(-5.5,4.5) H8(-4.5,4.5) H9(-3.5,4.5) H10(-2.5,4.5) H11(-1.5,4.5) H12(-0.5,4.5) H13(0.5,4.5) H14(1.5,4.5) H15(2.5,4.5) H16(3.5,4.5) H17(4.5,4.5) H18(5.5,4.5) H19(6.5,4.5) H20(7.5,4.5) H21(8.5,4.5) H22(9.5,4.5) H23(10.5,4.5) H24(11.5,4.5) J1(-11.5,3.5) J2(-10.5,3.5) J3(-9.5,3.5) J4(-8.5,3.5) J5(-7.5,3.5) J6(-6.5,3.5) J7(-5.5,3.5) J8(-4.5,3.5) J9(-3.5,3.5) J10(-2.5,3.5) J11(-1.5,3.5) J12(-0.5,3.5) J13(0.5,3.5) J14(1.5,3.5) J15(2.5,3.5) J16(3.5,3.5) J17(4.5,3.5) J18(5.5,3.5) J19(6.5,3.5) J20(7.5,3.5) J21(8.5,3.5) J22(9.5,3.5) J23(10.5,3.5) J24(11.5,3.5) K1(-11.5,2.5) K2(-10.5,2.5) K3(-9.5,2.5) K4(-8.5,2.5) K5(-7.5,2.5) K6(-6.5,2.5) K7(-5.5,2.5) K8(-4.5,2.5) K9(-3.5,2.5) K10(-2.5,2.5) K11(-1.5,2.5) K12(-0.5,2.5) K13(0.5,2.5) K14(1.5,2.5) K15(2.5,2.5) K16(3.5,2.5) K17(4.5,2.5) K18(5.5,2.5) K19(6.5,2.5) K20(7.5,2.5) K21(8.5,2.5) K22(9.5,2.5) K23(10.5,2.5) K24(11.5,2.5) L1(-11.5,1.5) L2(-10.5,1.5) L3(-9.5,1.5) L4(-8.5,1.5) L5(-7.5,1.5) L6(-6.5,1.5) L7(-5.5,1.5) L8(-4.5,1.5) L9(-3.5,1.5) L10(-2.5,1.5) L11(-1.5,1.5) L12(-0.5,1.5) L13(0.5,1.5) L14(1.5,1.5) L15(2.5,1.5) L16(3.5,1.5) L17(4.5,1.5) L18(5.5,1.5) L19(6.5,1.5) L20(7.5,1.5) L21(8.5,1.5) L22(9.5,1.5) L23(10.5,1.5) L24(11.5,1.5) M1(-11.5,0.5) M2(-10.5,0.5) M3(-9.5,0.5) M4(-8.5,0.5) M5(-7.5,0.5) M6(-6.5,0.5) M7(-5.5,0.5) M8(-4.5,0.5) M9(-3.5,0.5) M10(-2.5,0.5) M11(-1.5,0.5) M12(-0.5,0.5) M13(0.5,0.5) M14(1.5,0.5) M15(2.5,0.5) M16(3.5,0.5) M17(4.5,0.5) M18(5.5,0.5) M19(6.5,0.5) M20(7.5,0.5) M21(8.5,0.5) M22(9.5,0.5) M23(10.5,0.5) M24(11.5,0.5) N1(-11.5,-0.5) N2(-10.5,-0.5) N3(-9.5,-0.5) N4(-8.5,-0.5) N5(-7.5,-0.5) N6(-6.5,-0.5) N7(-5.5,-0.5) N8(-4.5,-0.5) N9(-3.5,-0.5) N10(-2.5,-0.5) N11(-1.5,-0.5) N12(-0.5,-0.5) N13(0.5,-0.5) N14(1.5,-0.5) N15(2.5,-0.5) N16(3.5,-0.5) N17(4.5,-0.5) N18(5.5,-0.5) N19(6.5,-0.5) N20(7.5,-0.5) N21(8.5,-0.5) N22(9.5,-0.5) N23(10.5,-0.5) N24(11.5,-0.5) P1(-11.5,-1.5) P2(-10.5,-1.5) P3(-9.5,-1.5) P4(-8.5,-1.5) P5(-7.5,-1.5) P6(-6.5,-1.5) P7(-5.5,-1.5) P8(-4.5,-1.5) P9(-3.5,-1.5) P10(-2.5,-1.5) P11(-1.5,-1.5) P12(-0.5,-1.5) P13(0.5,-1.5) P14(1.5,-1.5) P15(2.5,-1.5) P16(3.5,-1.5) P17(4.5,-1.5) P18(5.5,-1.5) P19(6.5,-1.5) P20(7.5,-1.5) P21(8.5,-1.5) P22(9.5,-1.5) P23(10.5,-1.5) P24(11.5,-1.5) R1(-11.5,-2.5) R2(-10.5,-2.5) R3(-9.5,-2.5) R4(-8.5,-2.5) R5(-7.5,-2.5) R6(-6.5,-2.5) R7(-5.5,-2.5) R8(-4.5,-2.5) R9(-3.5,-2.5) R10(-2.5,-2.5) R11(-1.5,-2.5) R12(-0.5,-2.5) R13(0.5,-2.5) R14(1.5,-2.5) R15(2.5,-2.5) R16(3.5,-2.5) R17(4.5,-2.5) R18(5.5,-2.5) R19(6.5,-2.5) R20(7.5,-2.5) R21(8.5,-2.5) R22(9.5,-2.5) R23(10.5,-2.5) R24(11.5,-2.5) T1(-11.5,-3.5) T2(-10.5,-3.5) T3(-9.5,-3.5) T4(-8.5,-3.5) T5(-7.5,-3.5) T6(-6.5,-3.5) T7(-5.5,-3.5) T8(-4.5,-3.5) T9(-3.5,-3.5) T10(-2.5,-3.5) T11(-1.5,-3.5) T12(-0.5,-3.5) T13(0.5,-3.5) T14(1.5,-3.5) T15(2.5,-3.5) T16(3.5,-3.5) T17(4.5,-3.5) T18(5.5,-3.5) T19(6.5,-3.5) T20(7.5,-3.5) T21(8.5,-3.5) T22(9.5,-3.5) T23(10.5,-3.5) T24(11.5,-3.5) U1(-11.5,-4.5) U2(-10.5,-4.5) U3(-9.5,-4.5) U4(-8.5,-4.5) U5(-7.5,-4.5) U6(-6.5,-4.5) U7(-5.5,-4.5) U8(-4.5,-4.5) U9(-3.5,-4.5) U10(-2.5,-4.5) U11(-1.5,-4.5) U12(-0.5,-4.5) U13(0.5,-4.5) U14(1.5,-4.5) U15(2.5,-4.5) U16(3.5,-4.5) U17(4.5,-4.5) U18(5.5,-4.5) U19(6.5,-4.5) U20(7.5,-4.5) U21(8.5,-4.5) U22(9.5,-4.5) U23(10.5,-4.5) U24(11.5,-4.5) V1(-11.5,-5.5) V2(-10.5,-5.5) V3(-9.5,-5.5) V4(-8.5,-5.5) V5(-7.5,-5.5) V6(-6.5,-5.5) V7(-5.5,-5.5) V8(-4.5,-5.5) V9(-3.5,-5.5) V10(-2.5,-5.5) V11(-1.5,-5.5) V12(-0.5,-5.5) V13(0.5,-5.5) V14(1.5,-5.5) V15(2.5,-5.5) V16(3.5,-5.5) V17(4.5,-5.5) V18(5.5,-5.5) V19(6.5,-5.5) V20(7.5,-5.5) V21(8.5,-5.5) V22(9.5,-5.5) V23(10.5,-5.5) V24(11.5,-5.5) W1(-11.5,-6.5) W2(-10.5,-6.5) W3(-9.5,-6.5) W4(-8.5,-6.5) W5(-7.5,-6.5) W6(-6.5,-6.5) W7(-5.5,-6.5) W8(-4.5,-6.5) W9(-3.5,-6.5) W10(-2.5,-6.5) W11(-1.5,-6.5) W12(-0.5,-6.5) W13(0.5,-6.5) W14(1.5,-6.5) W15(2.5,-6.5) W16(3.5,-6.5) W17(4.5,-6.5) W18(5.5,-6.5) W19(6.5,-6.5) W20(7.5,-6.5) W21(8.5,-6.5) W22(9.5,-6.5) W23(10.5,-6.5) W24(11.5,-6.5) Y1(-11.5,-7.5) Y2(-10.5,-7.5) Y3(-9.5,-7.5) Y4(-8.5,-7.5) Y5(-7.5,-7.5) Y6(-6.5,-7.5) Y7(-5.5,-7.5) Y8(-4.5,-7.5) Y9(-3.5,-7.5) Y10(-2.5,-7.5) Y11(-1.5,-7.5) Y12(-0.5,-7.5) Y13(0.5,-7.5) Y14(1.5,-7.5) Y15(2.5,-7.5) Y16(3.5,-7.5) Y17(4.5,-7.5) Y18(5.5,-7.5) Y19(6.5,-7.5) Y20(7.5,-7.5) Y21(8.5,-7.5) Y22(9.5,-7.5) Y23(10.5,-7.5) Y24(11.5,-7.5)
Top Overlay:
  circle w0.25: c-13.155,11.5 r0.125
  lines w0.2: -12.5,-11.5 -12.5,12.5 11.5,12.5 12.5,11.5 12.5,-11.5 11.5,-12.5 -11.5,-12.5 -12.5,-11.5

## BGA27X27-B352 [mm]
pads (352):
  round 0.5 smd: A1(-12.5,12.5) A2(-11.5,12.5) A3(-10.5,12.5) A4(-9.5,12.5) A5(-8.5,12.5) A6(-7.5,12.5) A7(-6.5,12.5) A8(-5.5,12.5) A9(-4.5,12.5) A10(-3.5,12.5) A11(-2.5,12.5) A12(-1.5,12.5) A13(-0.5,12.5) A14(0.5,12.5) A15(1.5,12.5) A16(2.5,12.5) A17(3.5,12.5) A18(4.5,12.5) A19(5.5,12.5) A20(6.5,12.5) A21(7.5,12.5) A22(8.5,12.5) A23(9.5,12.5) A24(10.5,12.5) A25(11.5,12.5) A26(12.5,12.5) AA1(-12.5,-7.5) AA2(-11.5,-7.5) AA3(-10.5,-7.5) AA4(-9.5,-7.5) AA23(9.5,-7.5) AA24(10.5,-7.5) AA25(11.5,-7.5) AA26(12.5,-7.5) AB1(-12.5,-8.5) AB2(-11.5,-8.5) AB3(-10.5,-8.5) AB4(-9.5,-8.5) AB23(9.5,-8.5) AB24(10.5,-8.5) AB25(11.5,-8.5) AB26(12.5,-8.5) AC1(-12.5,-9.5) AC2(-11.5,-9.5) AC3(-10.5,-9.5) AC4(-9.5,-9.5) AC5(-8.5,-9.5) AC6(-7.5,-9.5) AC7(-6.5,-9.5) AC8(-5.5,-9.5) AC9(-4.5,-9.5) AC10(-3.5,-9.5) AC11(-2.5,-9.5) AC12(-1.5,-9.5) AC13(-0.5,-9.5) AC14(0.5,-9.5) AC15(1.5,-9.5) AC16(2.5,-9.5) AC17(3.5,-9.5) AC18(4.5,-9.5) AC19(5.5,-9.5) AC20(6.5,-9.5) AC21(7.5,-9.5) AC22(8.5,-9.5) AC23(9.5,-9.5) AC24(10.5,-9.5) AC25(11.5,-9.5) AC26(12.5,-9.5) AD1(-12.5,-10.5) AD2(-11.5,-10.5) AD3(-10.5,-10.5) AD4(-9.5,-10.5) AD5(-8.5,-10.5) AD6(-7.5,-10.5) AD7(-6.5,-10.5) AD8(-5.5,-10.5) AD9(-4.5,-10.5) AD10(-3.5,-10.5) AD11(-2.5,-10.5) AD12(-1.5,-10.5) AD13(-0.5,-10.5) AD14(0.5,-10.5) AD15(1.5,-10.5) AD16(2.5,-10.5) AD17(3.5,-10.5) AD18(4.5,-10.5) AD19(5.5,-10.5) AD20(6.5,-10.5) AD21(7.5,-10.5) AD22(8.5,-10.5) AD23(9.5,-10.5) AD24(10.5,-10.5) AD25(11.5,-10.5) AD26(12.5,-10.5) AE1(-12.5,-11.5) AE2(-11.5,-11.5) AE3(-10.5,-11.5) AE4(-9.5,-11.5) AE5(-8.5,-11.5) AE6(-7.5,-11.5) AE7(-6.5,-11.5) AE8(-5.5,-11.5) AE9(-4.5,-11.5) AE10(-3.5,-11.5) AE11(-2.5,-11.5) AE12(-1.5,-11.5) AE13(-0.5,-11.5) AE14(0.5,-11.5) AE15(1.5,-11.5) AE16(2.5,-11.5) AE17(3.5,-11.5) AE18(4.5,-11.5) AE19(5.5,-11.5) AE20(6.5,-11.5) AE21(7.5,-11.5) AE22(8.5,-11.5) AE23(9.5,-11.5) AE24(10.5,-11.5) AE25(11.5,-11.5) AE26(12.5,-11.5) AF1(-12.5,-12.5) AF2(-11.5,-12.5) AF3(-10.5,-12.5) AF4(-9.5,-12.5) AF5(-8.5,-12.5) AF6(-7.5,-12.5) AF7(-6.5,-12.5) AF8(-5.5,-12.5) AF9(-4.5,-12.5) AF10(-3.5,-12.5) AF11(-2.5,-12.5) AF12(-1.5,-12.5) AF13(-0.5,-12.5) AF14(0.5,-12.5) AF15(1.5,-12.5) AF16(2.5,-12.5) AF17(3.5,-12.5) AF18(4.5,-12.5) AF19(5.5,-12.5) AF20(6.5,-12.5) AF21(7.5,-12.5) AF22(8.5,-12.5) AF23(9.5,-12.5) AF24(10.5,-12.5) AF25(11.5,-12.5) AF26(12.5,-12.5) B1(-12.5,11.5) B2(-11.5,11.5) B3(-10.5,11.5) B4(-9.5,11.5) B5(-8.5,11.5) B6(-7.5,11.5) B7(-6.5,11.5) B8(-5.5,11.5) B9(-4.5,11.5) B10(-3.5,11.5) B11(-2.5,11.5) B12(-1.5,11.5) B13(-0.5,11.5) B14(0.5,11.5) B15(1.5,11.5) B16(2.5,11.5) B17(3.5,11.5) B18(4.5,11.5) B19(5.5,11.5) B20(6.5,11.5) B21(7.5,11.5) B22(8.5,11.5) B23(9.5,11.5) B24(10.5,11.5) B25(11.5,11.5) B26(12.5,11.5) C1(-12.5,10.5) C2(-11.5,10.5) C3(-10.5,10.5) C4(-9.5,10.5) C5(-8.5,10.5) C6(-7.5,10.5) C7(-6.5,10.5) C8(-5.5,10.5) C9(-4.5,10.5) C10(-3.5,10.5) C11(-2.5,10.5) C12(-1.5,10.5) C13(-0.5,10.5) C14(0.5,10.5) C15(1.5,10.5) C16(2.5,10.5) C17(3.5,10.5) C18(4.5,10.5) C19(5.5,10.5) C20(6.5,10.5) C21(7.5,10.5) C22(8.5,10.5) C23(9.5,10.5) C24(10.5,10.5) C25(11.5,10.5) C26(12.5,10.5) D1(-12.5,9.5) D2(-11.5,9.5) D3(-10.5,9.5) D4(-9.5,9.5) D5(-8.5,9.5) D6(-7.5,9.5) D7(-6.5,9.5) D8(-5.5,9.5) D9(-4.5,9.5) D10(-3.5,9.5) D11(-2.5,9.5) D12(-1.5,9.5) D13(-0.5,9.5) D14(0.5,9.5) D15(1.5,9.5) D16(2.5,9.5) D17(3.5,9.5) D18(4.5,9.5) D19(5.5,9.5) D20(6.5,9.5) D21(7.5,9.5) D22(8.5,9.5) D23(9.5,9.5) D24(10.5,9.5) D25(11.5,9.5) D26(12.5,9.5) E1(-12.5,8.5) E2(-11.5,8.5) E3(-10.5,8.5) E4(-9.5,8.5) E23(9.5,8.5) E24(10.5,8.5) E25(11.5,8.5) E26(12.5,8.5) F1(-12.5,7.5) F2(-11.5,7.5) F3(-10.5,7.5) F4(-9.5,7.5) F23(9.5,7.5) F24(10.5,7.5) F25(11.5,7.5) F26(12.5,7.5) G1(-12.5,6.5) G2(-11.5,6.5) G3(-10.5,6.5) G4(-9.5,6.5) G23(9.5,6.5) G24(10.5,6.5) G25(11.5,6.5) G26(12.5,6.5) H1(-12.5,5.5) H2(-11.5,5.5) H3(-10.5,5.5) H4(-9.5,5.5) H23(9.5,5.5) H24(10.5,5.5) H25(11.5,5.5) H26(12.5,5.5) J1(-12.5,4.5) J2(-11.5,4.5) J3(-10.5,4.5) J4(-9.5,4.5) J23(9.5,4.5) J24(10.5,4.5) J25(11.5,4.5) J26(12.5,4.5) K1(-12.5,3.5) K2(-11.5,3.5) K3(-10.5,3.5) K4(-9.5,3.5) K23(9.5,3.5) K24(10.5,3.5) K25(11.5,3.5) K26(12.5,3.5) L1(-12.5,2.5) L2(-11.5,2.5) L3(-10.5,2.5) L4(-9.5,2.5) L23(9.5,2.5) L24(10.5,2.5) L25(11.5,2.5) L26(12.5,2.5) M1(-12.5,1.5) M2(-11.5,1.5) M3(-10.5,1.5) M4(-9.5,1.5) M23(9.5,1.5) M24(10.5,1.5) M25(11.5,1.5) M26(12.5,1.5) N1(-12.5,0.5) N2(-11.5,0.5) N3(-10.5,0.5) N4(-9.5,0.5) N23(9.5,0.5) N24(10.5,0.5) N25(11.5,0.5) N26(12.5,0.5) P1(-12.5,-0.5) P2(-11.5,-0.5) P3(-10.5,-0.5) P4(-9.5,-0.5) P23(9.5,-0.5) P24(10.5,-0.5) P25(11.5,-0.5) P26(12.5,-0.5) R1(-12.5,-1.5) R2(-11.5,-1.5) R3(-10.5,-1.5) R4(-9.5,-1.5) R23(9.5,-1.5) R24(10.5,-1.5) R25(11.5,-1.5) R26(12.5,-1.5) T1(-12.5,-2.5) T2(-11.5,-2.5) T3(-10.5,-2.5) T4(-9.5,-2.5) T23(9.5,-2.5) T24(10.5,-2.5) T25(11.5,-2.5) T26(12.5,-2.5) U1(-12.5,-3.5) U2(-11.5,-3.5) U3(-10.5,-3.5) U4(-9.5,-3.5) U23(9.5,-3.5) U24(10.5,-3.5) U25(11.5,-3.5) U26(12.5,-3.5) V1(-12.5,-4.5) V2(-11.5,-4.5) V3(-10.5,-4.5) V4(-9.5,-4.5) V23(9.5,-4.5) V24(10.5,-4.5) V25(11.5,-4.5) V26(12.5,-4.5) W1(-12.5,-5.5) W2(-11.5,-5.5) W3(-10.5,-5.5) W4(-9.5,-5.5) W23(9.5,-5.5) W24(10.5,-5.5) W25(11.5,-5.5) W26(12.5,-5.5) Y1(-12.5,-6.5) Y2(-11.5,-6.5) Y3(-10.5,-6.5) Y4(-9.5,-6.5) Y23(9.5,-6.5) Y24(10.5,-6.5) Y25(11.5,-6.5) Y26(12.5,-6.5)
Top Overlay:
  circle w0.25: c-14.15,12.5 r0.125
  lines w0.2: -13.5,-12.5 -12.5,-13.5 12.5,-13.5 13.5,-12.5 13.5,12.5 12.5,13.5 -13.5,13.5 -13.5,-12.5

## BGA27X27-B388 [mm]
pads (388):
  round 0.5 smd: A1(-12.5,12.5) A2(-11.5,12.5) A3(-10.5,12.5) A4(-9.5,12.5) A5(-8.5,12.5) A6(-7.5,12.5) A7(-6.5,12.5) A8(-5.5,12.5) A9(-4.5,12.5) A10(-3.5,12.5) A11(-2.5,12.5) A12(-1.5,12.5) A13(-0.5,12.5) A14(0.5,12.5) A15(1.5,12.5) A16(2.5,12.5) A17(3.5,12.5) A18(4.5,12.5) A19(5.5,12.5) A20(6.5,12.5) A21(7.5,12.5) A22(8.5,12.5) A23(9.5,12.5) A24(10.5,12.5) A25(11.5,12.5) A26(12.5,12.5) AA1(-12.5,-7.5) AA2(-11.5,-7.5) AA3(-10.5,-7.5) AA4(-9.5,-7.5) AA23(9.5,-7.5) AA24(10.5,-7.5) AA25(11.5,-7.5) AA26(12.5,-7.5) AB1(-12.5,-8.5) AB2(-11.5,-8.5) AB3(-10.5,-8.5) AB4(-9.5,-8.5) AB23(9.5,-8.5) AB24(10.5,-8.5) AB25(11.5,-8.5) AB26(12.5,-8.5) AC1(-12.5,-9.5) AC2(-11.5,-9.5) AC3(-10.5,-9.5) AC4(-9.5,-9.5) AC5(-8.5,-9.5) AC6(-7.5,-9.5) AC7(-6.5,-9.5) AC8(-5.5,-9.5) AC9(-4.5,-9.5) AC10(-3.5,-9.5) AC11(-2.5,-9.5) AC12(-1.5,-9.5) AC13(-0.5,-9.5) AC14(0.5,-9.5) AC15(1.5,-9.5) AC16(2.5,-9.5) AC17(3.5,-9.5) AC18(4.5,-9.5) AC19(5.5,-9.5) AC20(6.5,-9.5) AC21(7.5,-9.5) AC22(8.5,-9.5) AC23(9.5,-9.5) AC24(10.5,-9.5) AC25(11.5,-9.5) AC26(12.5,-9.5) AD1(-12.5,-10.5) AD2(-11.5,-10.5) AD3(-10.5,-10.5) AD4(-9.5,-10.5) AD5(-8.5,-10.5) AD6(-7.5,-10.5) AD7(-6.5,-10.5) AD8(-5.5,-10.5) AD9(-4.5,-10.5) AD10(-3.5,-10.5) AD11(-2.5,-10.5) AD12(-1.5,-10.5) AD13(-0.5,-10.5) AD14(0.5,-10.5) AD15(1.5,-10.5) AD16(2.5,-10.5) AD17(3.5,-10.5) AD18(4.5,-10.5) AD19(5.5,-10.5) AD20(6.5,-10.5) AD21(7.5,-10.5) AD22(8.5,-10.5) AD23(9.5,-10.5) AD24(10.5,-10.5) AD25(11.5,-10.5) AD26(12.5,-10.5) AE1(-12.5,-11.5) AE2(-11.5,-11.5) AE3(-10.5,-11.5) AE4(-9.5,-11.5) AE5(-8.5,-11.5) AE6(-7.5,-11.5) AE7(-6.5,-11.5) AE8(-5.5,-11.5) AE9(-4.5,-11.5) AE10(-3.5,-11.5) AE11(-2.5,-11.5) AE12(-1.5,-11.5) AE13(-0.5,-11.5) AE14(0.5,-11.5) AE15(1.5,-11.5) AE16(2.5,-11.5) AE17(3.5,-11.5) AE18(4.5,-11.5) AE19(5.5,-11.5) AE20(6.5,-11.5) AE21(7.5,-11.5) AE22(8.5,-11.5) AE23(9.5,-11.5) AE24(10.5,-11.5) AE25(11.5,-11.5) AE26(12.5,-11.5) AF1(-12.5,-12.5) AF2(-11.5,-12.5) AF3(-10.5,-12.5) AF4(-9.5,-12.5) AF5(-8.5,-12.5) AF6(-7.5,-12.5) AF7(-6.5,-12.5) AF8(-5.5,-12.5) AF9(-4.5,-12.5) AF10(-3.5,-12.5) AF11(-2.5,-12.5) AF12(-1.5,-12.5) AF13(-0.5,-12.5) AF14(0.5,-12.5) AF15(1.5,-12.5) AF16(2.5,-12.5) AF17(3.5,-12.5) AF18(4.5,-12.5) AF19(5.5,-12.5) AF20(6.5,-12.5) AF21(7.5,-12.5) AF22(8.5,-12.5) AF23(9.5,-12.5) AF24(10.5,-12.5) AF25(11.5,-12.5) AF26(12.5,-12.5) B1(-12.5,11.5) B2(-11.5,11.5) B3(-10.5,11.5) B4(-9.5,11.5) B5(-8.5,11.5) B6(-7.5,11.5) B7(-6.5,11.5) B8(-5.5,11.5) B9(-4.5,11.5) B10(-3.5,11.5) B11(-2.5,11.5) B12(-1.5,11.5) B13(-0.5,11.5) B14(0.5,11.5) B15(1.5,11.5) B16(2.5,11.5) B17(3.5,11.5) B18(4.5,11.5) B19(5.5,11.5) B20(6.5,11.5) B21(7.5,11.5) B22(8.5,11.5) B23(9.5,11.5) B24(10.5,11.5) B25(11.5,11.5) B26(12.5,11.5) C1(-12.5,10.5) C2(-11.5,10.5) C3(-10.5,10.5) C4(-9.5,10.5) C5(-8.5,10.5) C6(-7.5,10.5) C7(-6.5,10.5) C8(-5.5,10.5) C9(-4.5,10.5) C10(-3.5,10.5) C11(-2.5,10.5) C12(-1.5,10.5) C13(-0.5,10.5) C14(0.5,10.5) C15(1.5,10.5) C16(2.5,10.5) C17(3.5,10.5) C18(4.5,10.5) C19(5.5,10.5) C20(6.5,10.5) C21(7.5,10.5) C22(8.5,10.5) C23(9.5,10.5) C24(10.5,10.5) C25(11.5,10.5) C26(12.5,10.5) D1(-12.5,9.5) D2(-11.5,9.5) D3(-10.5,9.5) D4(-9.5,9.5) D5(-8.5,9.5) D6(-7.5,9.5) D7(-6.5,9.5) D8(-5.5,9.5) D9(-4.5,9.5) D10(-3.5,9.5) D11(-2.5,9.5) D12(-1.5,9.5) D13(-0.5,9.5) D14(0.5,9.5) D15(1.5,9.5) D16(2.5,9.5) D17(3.5,9.5) D18(4.5,9.5) D19(5.5,9.5) D20(6.5,9.5) D21(7.5,9.5) D22(8.5,9.5) D23(9.5,9.5) D24(10.5,9.5) D25(11.5,9.5) D26(12.5,9.5) E1(-12.5,8.5) E2(-11.5,8.5) E3(-10.5,8.5) E4(-9.5,8.5) E23(9.5,8.5) E24(10.5,8.5) E25(11.5,8.5) E26(12.5,8.5) F1(-12.5,7.5) F2(-11.5,7.5) F3(-10.5,7.5) F4(-9.5,7.5) F23(9.5,7.5) F24(10.5,7.5) F25(11.5,7.5) F26(12.5,7.5) G1(-12.5,6.5) G2(-11.5,6.5) G3(-10.5,6.5) G4(-9.5,6.5) G23(9.5,6.5) G24(10.5,6.5) G25(11.5,6.5) G26(12.5,6.5) H1(-12.5,5.5) H2(-11.5,5.5) H3(-10.5,5.5) H4(-9.5,5.5) H23(9.5,5.5) H24(10.5,5.5) H25(11.5,5.5) H26(12.5,5.5) J1(-12.5,4.5) J2(-11.5,4.5) J3(-10.5,4.5) J4(-9.5,4.5) J23(9.5,4.5) J24(10.5,4.5) J25(11.5,4.5) J26(12.5,4.5) K1(-12.5,3.5) K2(-11.5,3.5) K3(-10.5,3.5) K4(-9.5,3.5) K23(9.5,3.5) K24(10.5,3.5) K25(11.5,3.5) K26(12.5,3.5) L1(-12.5,2.5) L2(-11.5,2.5) L3(-10.5,2.5) L4(-9.5,2.5) L11(-2.5,2.5) L12(-1.5,2.5) L13(-0.5,2.5) L14(0.5,2.5) L15(1.5,2.5) L16(2.5,2.5) L23(9.5,2.5) L24(10.5,2.5) L25(11.5,2.5) L26(12.5,2.5) M1(-12.5,1.5) M2(-11.5,1.5) M3(-10.5,1.5) M4(-9.5,1.5) M11(-2.5,1.5) M12(-1.5,1.5) M13(-0.5,1.5) M14(0.5,1.5) M15(1.5,1.5) M16(2.5,1.5) M23(9.5,1.5) M24(10.5,1.5) M25(11.5,1.5) M26(12.5,1.5) N1(-12.5,0.5) N2(-11.5,0.5) N3(-10.5,0.5) N4(-9.5,0.5) N11(-2.5,0.5) N12(-1.5,0.5) N13(-0.5,0.5) N14(0.5,0.5) N15(1.5,0.5) N16(2.5,0.5) N23(9.5,0.5) N24(10.5,0.5) N25(11.5,0.5) N26(12.5,0.5) P1(-12.5,-0.5) P2(-11.5,-0.5) P3(-10.5,-0.5) P4(-9.5,-0.5) P11(-2.5,-0.5) P12(-1.5,-0.5) P13(-0.5,-0.5) P14(0.5,-0.5) P15(1.5,-0.5) P16(2.5,-0.5) P23(9.5,-0.5) P24(10.5,-0.5) P25(11.5,-0.5) P26(12.5,-0.5) R1(-12.5,-1.5) R2(-11.5,-1.5) R3(-10.5,-1.5) R4(-9.5,-1.5) R11(-2.5,-1.5) R12(-1.5,-1.5) R13(-0.5,-1.5) R14(0.5,-1.5) R15(1.5,-1.5) R16(2.5,-1.5) R23(9.5,-1.5) R24(10.5,-1.5) R25(11.5,-1.5) R26(12.5,-1.5) T1(-12.5,-2.5) T2(-11.5,-2.5) T3(-10.5,-2.5) T4(-9.5,-2.5) T11(-2.5,-2.5) T12(-1.5,-2.5) T13(-0.5,-2.5) T14(0.5,-2.5) T15(1.5,-2.5) T16(2.5,-2.5) T23(9.5,-2.5) T24(10.5,-2.5) T25(11.5,-2.5) T26(12.5,-2.5) U1(-12.5,-3.5) U2(-11.5,-3.5) U3(-10.5,-3.5) U4(-9.5,-3.5) U23(9.5,-3.5) U24(10.5,-3.5) U25(11.5,-3.5) U26(12.5,-3.5) V1(-12.5,-4.5) V2(-11.5,-4.5) V3(-10.5,-4.5) V4(-9.5,-4.5) V23(9.5,-4.5) V24(10.5,-4.5) V25(11.5,-4.5) V26(12.5,-4.5) W1(-12.5,-5.5) W2(-11.5,-5.5) W3(-10.5,-5.5) W4(-9.5,-5.5) W23(9.5,-5.5) W24(10.5,-5.5) W25(11.5,-5.5) W26(12.5,-5.5) Y1(-12.5,-6.5) Y2(-11.5,-6.5) Y3(-10.5,-6.5) Y4(-9.5,-6.5) Y23(9.5,-6.5) Y24(10.5,-6.5) Y25(11.5,-6.5) Y26(12.5,-6.5)
Top Overlay:
  circle w0.25: c-14.15,12.5 r0.125
  lines w0.2: -13.5,-12.5 -12.5,-13.5 12.5,-13.5 13.5,-12.5 13.5,12.5 12.5,13.5 -13.5,13.5 -13.5,-12.5

## BGA27X27-B452 [mm]
pads (452):
  round 0.5 smd: A1(-12.5,12.5) A2(-11.5,12.5) A3(-10.5,12.5) A4(-9.5,12.5) A5(-8.5,12.5) A6(-7.5,12.5) A7(-6.5,12.5) A8(-5.5,12.5) A9(-4.5,12.5) A10(-3.5,12.5) A11(-2.5,12.5) A12(-1.5,12.5) A13(-0.5,12.5) A14(0.5,12.5) A15(1.5,12.5) A16(2.5,12.5) A17(3.5,12.5) A18(4.5,12.5) A19(5.5,12.5) A20(6.5,12.5) A21(7.5,12.5) A22(8.5,12.5) A23(9.5,12.5) A24(10.5,12.5) A25(11.5,12.5) A26(12.5,12.5) AA1(-12.5,-7.5) AA2(-11.5,-7.5) AA3(-10.5,-7.5) AA4(-9.5,-7.5) AA23(9.5,-7.5) AA24(10.5,-7.5) AA25(11.5,-7.5) AA26(12.5,-7.5) AB1(-12.5,-8.5) AB2(-11.5,-8.5) AB3(-10.5,-8.5) AB4(-9.5,-8.5) AB23(9.5,-8.5) AB24(10.5,-8.5) AB25(11.5,-8.5) AB26(12.5,-8.5) AC1(-12.5,-9.5) AC2(-11.5,-9.5) AC3(-10.5,-9.5) AC4(-9.5,-9.5) AC5(-8.5,-9.5) AC6(-7.5,-9.5) AC7(-6.5,-9.5) AC8(-5.5,-9.5) AC9(-4.5,-9.5) AC10(-3.5,-9.5) AC11(-2.5,-9.5) AC12(-1.5,-9.5) AC13(-0.5,-9.5) AC14(0.5,-9.5) AC15(1.5,-9.5) AC16(2.5,-9.5) AC17(3.5,-9.5) AC18(4.5,-9.5) AC19(5.5,-9.5) AC20(6.5,-9.5) AC21(7.5,-9.5) AC22(8.5,-9.5) AC23(9.5,-9.5) AC24(10.5,-9.5) AC25(11.5,-9.5) AC26(12.5,-9.5) AD1(-12.5,-10.5) AD2(-11.5,-10.5) AD3(-10.5,-10.5) AD4(-9.5,-10.5) AD5(-8.5,-10.5) AD6(-7.5,-10.5) AD7(-6.5,-10.5) AD8(-5.5,-10.5) AD9(-4.5,-10.5) AD10(-3.5,-10.5) AD11(-2.5,-10.5) AD12(-1.5,-10.5) AD13(-0.5,-10.5) AD14(0.5,-10.5) AD15(1.5,-10.5) AD16(2.5,-10.5) AD17(3.5,-10.5) AD18(4.5,-10.5) AD19(5.5,-10.5) AD20(6.5,-10.5) AD21(7.5,-10.5) AD22(8.5,-10.5) AD23(9.5,-10.5) AD24(10.5,-10.5) AD25(11.5,-10.5) AD26(12.5,-10.5) AE1(-12.5,-11.5) AE2(-11.5,-11.5) AE3(-10.5,-11.5) AE4(-9.5,-11.5) AE5(-8.5,-11.5) AE6(-7.5,-11.5) AE7(-6.5,-11.5) AE8(-5.5,-11.5) AE9(-4.5,-11.5) AE10(-3.5,-11.5) AE11(-2.5,-11.5) AE12(-1.5,-11.5) AE13(-0.5,-11.5) AE14(0.5,-11.5) AE15(1.5,-11.5) AE16(2.5,-11.5) AE17(3.5,-11.5) AE18(4.5,-11.5) AE19(5.5,-11.5) AE20(6.5,-11.5) AE21(7.5,-11.5) AE22(8.5,-11.5) AE23(9.5,-11.5) AE24(10.5,-11.5) AE25(11.5,-11.5) AE26(12.5,-11.5) AF1(-12.5,-12.5) AF2(-11.5,-12.5) AF3(-10.5,-12.5) AF4(-9.5,-12.5) AF5(-8.5,-12.5) AF6(-7.5,-12.5) AF7(-6.5,-12.5) AF8(-5.5,-12.5) AF9(-4.5,-12.5) AF10(-3.5,-12.5) AF11(-2.5,-12.5) AF12(-1.5,-12.5) AF13(-0.5,-12.5) AF14(0.5,-12.5) AF15(1.5,-12.5) AF16(2.5,-12.5) AF17(3.5,-12.5) AF18(4.5,-12.5) AF19(5.5,-12.5) AF20(6.5,-12.5) AF21(7.5,-12.5) AF22(8.5,-12.5) AF23(9.5,-12.5) AF24(10.5,-12.5) AF25(11.5,-12.5) AF26(12.5,-12.5) B1(-12.5,11.5) B2(-11.5,11.5) B3(-10.5,11.5) B4(-9.5,11.5) B5(-8.5,11.5) B6(-7.5,11.5) B7(-6.5,11.5) B8(-5.5,11.5) B9(-4.5,11.5) B10(-3.5,11.5) B11(-2.5,11.5) B12(-1.5,11.5) B13(-0.5,11.5) B14(0.5,11.5) B15(1.5,11.5) B16(2.5,11.5) B17(3.5,11.5) B18(4.5,11.5) B19(5.5,11.5) B20(6.5,11.5) B21(7.5,11.5) B22(8.5,11.5) B23(9.5,11.5) B24(10.5,11.5) B25(11.5,11.5) B26(12.5,11.5) C1(-12.5,10.5) C2(-11.5,10.5) C3(-10.5,10.5) C4(-9.5,10.5) C5(-8.5,10.5) C6(-7.5,10.5) C7(-6.5,10.5) C8(-5.5,10.5) C9(-4.5,10.5) C10(-3.5,10.5) C11(-2.5,10.5) C12(-1.5,10.5) C13(-0.5,10.5) C14(0.5,10.5) C15(1.5,10.5) C16(2.5,10.5) C17(3.5,10.5) C18(4.5,10.5) C19(5.5,10.5) C20(6.5,10.5) C21(7.5,10.5) C22(8.5,10.5) C23(9.5,10.5) C24(10.5,10.5) C25(11.5,10.5) C26(12.5,10.5) D1(-12.5,9.5) D2(-11.5,9.5) D3(-10.5,9.5) D4(-9.5,9.5) D5(-8.5,9.5) D6(-7.5,9.5) D7(-6.5,9.5) D8(-5.5,9.5) D9(-4.5,9.5) D10(-3.5,9.5) D11(-2.5,9.5) D12(-1.5,9.5) D13(-0.5,9.5) D14(0.5,9.5) D15(1.5,9.5) D16(2.5,9.5) D17(3.5,9.5) D18(4.5,9.5) D19(5.5,9.5) D20(6.5,9.5) D21(7.5,9.5) D22(8.5,9.5) D23(9.5,9.5) D24(10.5,9.5) D25(11.5,9.5) D26(12.5,9.5) E1(-12.5,8.5) E2(-11.5,8.5) E3(-10.5,8.5) E4(-9.5,8.5) E23(9.5,8.5) E24(10.5,8.5) E25(11.5,8.5) E26(12.5,8.5) F1(-12.5,7.5) F2(-11.5,7.5) F3(-10.5,7.5) F4(-9.5,7.5) F23(9.5,7.5) F24(10.5,7.5) F25(11.5,7.5) F26(12.5,7.5) G1(-12.5,6.5) G2(-11.5,6.5) G3(-10.5,6.5) G4(-9.5,6.5) G23(9.5,6.5) G24(10.5,6.5) G25(11.5,6.5) G26(12.5,6.5) H1(-12.5,5.5) H2(-11.5,5.5) H3(-10.5,5.5) H4(-9.5,5.5) H23(9.5,5.5) H24(10.5,5.5) H25(11.5,5.5) H26(12.5,5.5) J1(-12.5,4.5) J2(-11.5,4.5) J3(-10.5,4.5) J4(-9.5,4.5) J9(-4.5,4.5) J10(-3.5,4.5) J11(-2.5,4.5) J12(-1.5,4.5) J13(-0.5,4.5) J14(0.5,4.5) J15(1.5,4.5) J16(2.5,4.5) J17(3.5,4.5) J18(4.5,4.5) J23(9.5,4.5) J24(10.5,4.5) J25(11.5,4.5) J26(12.5,4.5) K1(-12.5,3.5) K2(-11.5,3.5) K3(-10.5,3.5) K4(-9.5,3.5) K9(-4.5,3.5) K10(-3.5,3.5) K11(-2.5,3.5) K12(-1.5,3.5) K13(-0.5,3.5) K14(0.5,3.5) K15(1.5,3.5) K16(2.5,3.5) K17(3.5,3.5) K18(4.5,3.5) K23(9.5,3.5) K24(10.5,3.5) K25(11.5,3.5) K26(12.5,3.5) L1(-12.5,2.5) L2(-11.5,2.5) L3(-10.5,2.5) L4(-9.5,2.5) L9(-4.5,2.5) L10(-3.5,2.5) L11(-2.5,2.5) L12(-1.5,2.5) L13(-0.5,2.5) L14(0.5,2.5) L15(1.5,2.5) L16(2.5,2.5) L17(3.5,2.5) L18(4.5,2.5) L23(9.5,2.5) L24(10.5,2.5) L25(11.5,2.5) L26(12.5,2.5) M1(-12.5,1.5) M2(-11.5,1.5) M3(-10.5,1.5) M4(-9.5,1.5) M9(-4.5,1.5) M10(-3.5,1.5) M11(-2.5,1.5) M12(-1.5,1.5) M13(-0.5,1.5) M14(0.5,1.5) M15(1.5,1.5) M16(2.5,1.5) M17(3.5,1.5) M18(4.5,1.5) M23(9.5,1.5) M24(10.5,1.5) M25(11.5,1.5) M26(12.5,1.5) N1(-12.5,0.5) N2(-11.5,0.5) N3(-10.5,0.5) N4(-9.5,0.5) N9(-4.5,0.5) N10(-3.5,0.5) N11(-2.5,0.5) N12(-1.5,0.5) N13(-0.5,0.5) N14(0.5,0.5) N15(1.5,0.5) N16(2.5,0.5) N17(3.5,0.5) N18(4.5,0.5) N23(9.5,0.5) N24(10.5,0.5) N25(11.5,0.5) N26(12.5,0.5) P1(-12.5,-0.5) P2(-11.5,-0.5) P3(-10.5,-0.5) P4(-9.5,-0.5) P9(-4.5,-0.5) P10(-3.5,-0.5) P11(-2.5,-0.5) P12(-1.5,-0.5) P13(-0.5,-0.5) P14(0.5,-0.5) P15(1.5,-0.5) P16(2.5,-0.5) P17(3.5,-0.5) P18(4.5,-0.5) P23(9.5,-0.5) P24(10.5,-0.5) P25(11.5,-0.5) P26(12.5,-0.5) R1(-12.5,-1.5) R2(-11.5,-1.5) R3(-10.5,-1.5) R4(-9.5,-1.5) R9(-4.5,-1.5) R10(-3.5,-1.5) R11(-2.5,-1.5) R12(-1.5,-1.5) R13(-0.5,-1.5) R14(0.5,-1.5) R15(1.5,-1.5) R16(2.5,-1.5) R17(3.5,-1.5) R18(4.5,-1.5) R23(9.5,-1.5) R24(10.5,-1.5) R25(11.5,-1.5) R26(12.5,-1.5) T1(-12.5,-2.5) T2(-11.5,-2.5) T3(-10.5,-2.5) T4(-9.5,-2.5) T9(-4.5,-2.5) T10(-3.5,-2.5) T11(-2.5,-2.5) T12(-1.5,-2.5) T13(-0.5,-2.5) T14(0.5,-2.5) T15(1.5,-2.5) T16(2.5,-2.5) T17(3.5,-2.5) T18(4.5,-2.5) T23(9.5,-2.5) T24(10.5,-2.5) T25(11.5,-2.5) T26(12.5,-2.5) U1(-12.5,-3.5) U2(-11.5,-3.5) U3(-10.5,-3.5) U4(-9.5,-3.5) U9(-4.5,-3.5) U10(-3.5,-3.5) U11(-2.5,-3.5) U12(-1.5,-3.5) U13(-0.5,-3.5) U14(0.5,-3.5) U15(1.5,-3.5) U16(2.5,-3.5) U17(3.5,-3.5) U18(4.5,-3.5) U23(9.5,-3.5) U24(10.5,-3.5) U25(11.5,-3.5) U26(12.5,-3.5) V1(-12.5,-4.5) V2(-11.5,-4.5) V3(-10.5,-4.5) V4(-9.5,-4.5) V9(-4.5,-4.5) V10(-3.5,-4.5) V11(-2.5,-4.5) V12(-1.5,-4.5) V13(-0.5,-4.5) V14(0.5,-4.5) V15(1.5,-4.5) V16(2.5,-4.5) V17(3.5,-4.5) V18(4.5,-4.5) V23(9.5,-4.5) V24(10.5,-4.5) V25(11.5,-4.5) V26(12.5,-4.5) W1(-12.5,-5.5) W2(-11.5,-5.5) W3(-10.5,-5.5) W4(-9.5,-5.5) W23(9.5,-5.5) W24(10.5,-5.5) W25(11.5,-5.5) W26(12.5,-5.5) Y1(-12.5,-6.5) Y2(-11.5,-6.5) Y3(-10.5,-6.5) Y4(-9.5,-6.5) Y23(9.5,-6.5) Y24(10.5,-6.5) Y25(11.5,-6.5) Y26(12.5,-6.5)
Top Overlay:
  circle w0.25: c-14.15,12.5 r0.125
  lines w0.2: -13.5,-12.5 -12.5,-13.5 12.5,-13.5 13.5,-12.5 13.5,12.5 12.5,13.5 -13.5,13.5 -13.5,-12.5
